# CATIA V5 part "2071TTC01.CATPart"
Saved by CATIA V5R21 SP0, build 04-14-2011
Part number: 2071TTC01
Bounding box of the stored display mesh (mm): x -19 to 19, y 0 to 1000, z -28.5 to 25.5
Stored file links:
  C:\Users\ALI OZGUN\Desktop\alhan\PROFILLER\2071TTC01.CATPart
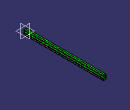
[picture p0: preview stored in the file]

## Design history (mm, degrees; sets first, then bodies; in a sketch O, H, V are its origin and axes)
Set1
  DatumSurface1
Body1 (main body)
  Sketch1 on zx-plane, origin (0, 0, 0), H (-1, 0, 0), V (0, 0, 1)
    line L1 (19, 22.6) -> (19, -25.5)
    line L2 (19, -25.5) -> (-19, -25.5)
    line L3 (-19, -25.5) -> (-19, -1.5)
    line L4 (-19, 25.5) -> (-2.5, 25.5)
    point P4 (-19, 6.5)
    line L5 (-2.5, -1.5) -> (-19, -1.5)
    line L6 (-19, 14.5) -> (-2.5, 14.5)
    point P5 (-9.0936, 12.527)
    point P6 (2.75, 6.5)
    line L7 (8, 17.5) -> (8, -4.5)
    line L8 (8, -4.5) -> (-2.5, -4.5)
    line L9 (-2.5, -4.5) -> (-2.5, -1.5)
    line L10 (-2.5, 17.5) -> (8, 17.5)
    line L11 (19, 22.6) -> (-2.5, 22.6)
    line L12 (-2.5, 22.6) -> (-2.5, 25.5)
    axis line L13 (-44.5224, 6.5) -> (23.1973, 6.5)
    line L14 (-19, 14.5) -> (-19, 25.5)
    point P18 (-2.5, 14.5)
    line L15 (-2.5, 14.5) -> (-2.5, 17.5)
    distance L6 L5 = 16
    distance L10 L8 = 22
    distance L7 L9 = 10.5
    distance L12 L3 = 16.5
    distance L1 L3 = 38
    distance L4 L2 = 51
    distance L11 L4 = 2.9
    distance L4 L13 = 19
    vertical: L1 V, L3 V, L7 V, L9 V, L12 V, L14 V, L15 V
    horizontal: L2 H, L4 H, L5 H, L6 H, L8 H, L10 H, L11 H, L13 H
    equidistance: L1 L3 O, L2 L4 O, L5 L6 P4, L7 L9 P6, L8 L10 P6
    coincidence: P4 L3, L9 L12, L3 L14, L9 P18, L9 L15
    symmetry: L6 L5 L13, L8 L10 L13
  Pad1: profile Sketch1, direction (0, 1, 0), length 1000
  Body2
    Solid1: linked copy from another document
  Remove1: tool Body2
  RemoveFace1: RemoveFaces (face of Solid1; face of Solid1)
Body3
  Sketch2 on start face of Pad1, origin (0, 0, 0), H (1, 0, 0), V (0, 0, 1)
    point P1 (0, -19.5)
    line L1 (19, -11.5) -> (19, -27.5)
    line L2 (18, -28.5) -> (-18, -28.5)
    line L3 (-19, -27.5) -> (-19, -11.5)
    line L4 (10, -10.5) -> (18, -10.5)
    point P2 (-19, -10.5)
    point P3 (10, -10.5)
    line L5 (-18, -10.5) -> (-10, -10.5)
    point P4 (-10, -10.5)
    reference projected line E1 (2.5, 25.5) -> (19, 25.5) from edge [start face of Pad1 | face of Pad1 from Sketch1.L4]
    arc A1 centre (18, -11.5) radius 1 from (19, -11.5) to (18, -10.5) ccw
    arc A2 centre (18, -27.5) radius 1 from (19, -27.5) to (18, -28.5) cw
    arc A3 centre (-18, -27.5) radius 1 from (-18, -28.5) to (-19, -27.5) cw
    arc A4 centre (-18, -11.5) radius 1 from (-19, -11.5) to (-18, -10.5) cw
    distance P3 P4 = 20
    distance L4 L2 = 18
    distance L1 L3 = 38
    distance L2 E1 = 54
    radius A1 = 1
    radius A2 = 1 {= Sketch2.radius(A1)}
    radius A3 = 1 {= Sketch2.radius(A1)}
    radius A4 = 1 {= Sketch2.radius(A1)}
    coincidence: P1 V, P2 L4, L3 P2, L5 P2
    vertical: L1 V, L3 V
    horizontal: L2 H, L4 H, L5 H
    equidistance: L1 L3 P1, L2 L4 P1
    symmetry: P3 P4 V
    tangency: A1 L1, A1 L4, A2 L1, A2 L2, A3 L2, A3 L3, A4 L3, A4 L5
  Pad2: profile Sketch2, direction (0, 1, 0), length 1000, thin wall 1.5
